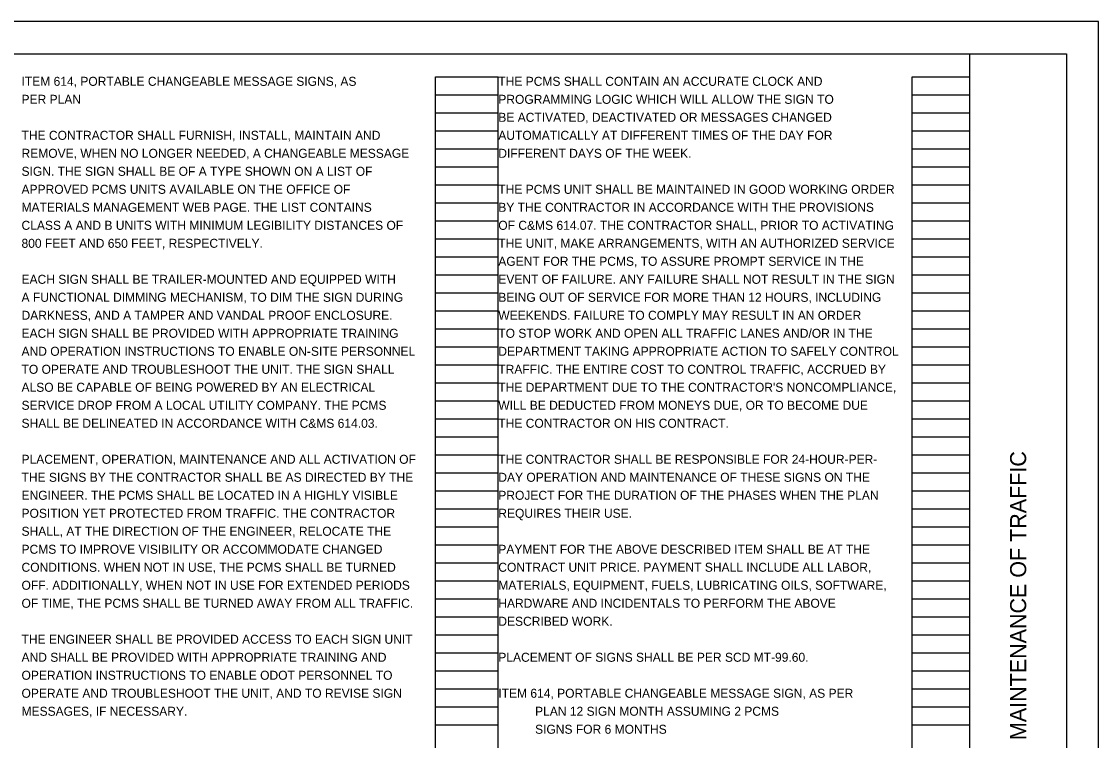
# Model space of a CAD drawing. Extents: x 0 to 34, y 0 to 22.
# Drawn here: x 17.24 to 34, y 10.82 to 22 of the extents above; entities that cross this region are included whole.
import ezdxf

# ---------------------------------------------------------------- set-up
doc = ezdxf.new("R2010")
doc.units = 0
for name, color, linetype in [('SH_Border', 7, 'Continuous'), ('SH_Cut_Line', 7, 'Continuous'), ('SH_Data', 7, 'Continuous'), ('SH_Text', 7, 'Continuous')]:
    doc.layers.add(name, color=color, linetype=linetype)

msp = doc.modelspace()

# ---------------------------------------------------------------- linework, layer by layer
at = {"layer": 'SH_Border'}
msp.add_line((32, 0.5), (32, 21.5), dxfattribs=at)
msp.add_lwpolyline([(1.5, 21.5), (33.5, 21.5), (33.5, 0.5), (1.5, 0.5)], close=True, dxfattribs=at)
at = {"layer": 'SH_Cut_Line'}
msp.add_lwpolyline([(0, 0), (34, 0), (34, 22), (0, 22)], close=True, dxfattribs=at)
at = {"layer": 'SH_Data'}
for p, q in [((23.68, 0.98), (23.68, 21.14)), ((23.68, 21.14), (24.66, 21.14)), ((24.66, 0.98), (24.66, 21.14)), ((31.1, 0.98), (31.1, 21.14)), ((31.1, 21.14), (32, 21.14)), ((32, 0.98), (32, 21.14)), ((23.68, 20.86), (24.66, 20.86)), ((31.1, 20.86), (32, 20.86)), ((23.68, 20.58), (24.66, 20.58)), ((31.1, 20.58), (32, 20.58)), ((23.68, 20.3), (24.66, 20.3)), ((31.1, 20.3), (32, 20.3)), ((23.68, 20.02), (24.66, 20.02)), ((31.1, 20.02), (32, 20.02)), ((23.68, 19.74), (24.66, 19.74)), ((31.1, 19.74), (32, 19.74)), ((23.68, 19.46), (24.66, 19.46)), ((31.1, 19.46), (32, 19.46)), ((23.68, 19.18), (24.66, 19.18)), ((31.1, 19.18), (32, 19.18)), ((23.68, 18.9), (24.66, 18.9)), ((31.1, 18.9), (32, 18.9)), ((23.68, 18.62), (24.66, 18.62)), ((31.1, 18.62), (32, 18.62)), ((23.68, 18.34), (24.66, 18.34)), ((31.1, 18.34), (32, 18.34)), ((23.68, 18.06), (24.66, 18.06)), ((31.1, 18.06), (32, 18.06)), ((23.68, 17.78), (24.66, 17.78)), ((31.1, 17.78), (32, 17.78)), ((23.68, 17.5), (24.66, 17.5)), ((31.1, 17.5), (32, 17.5)), ((23.68, 17.22), (24.66, 17.22)), ((31.1, 17.22), (32, 17.22)), ((23.68, 16.94), (24.66, 16.94)), ((31.1, 16.94), (32, 16.94)), ((23.68, 16.66), (24.66, 16.66)), ((31.1, 16.66), (32, 16.66)), ((23.68, 16.38), (24.66, 16.38)), ((31.1, 16.38), (32, 16.38)), ((23.68, 16.1), (24.66, 16.1)), ((31.1, 16.1), (32, 16.1)), ((23.68, 15.82), (24.66, 15.82)), ((31.1, 15.82), (32, 15.82)), ((23.68, 15.54), (24.66, 15.54)), ((31.1, 15.54), (32, 15.54)), ((23.68, 15.26), (24.66, 15.26)), ((31.1, 15.26), (32, 15.26)), ((23.68, 14.98), (24.66, 14.98)), ((31.1, 14.98), (32, 14.98)), ((23.68, 14.7), (24.66, 14.7)), ((31.1, 14.7), (32, 14.7)), ((23.68, 14.42), (24.66, 14.42)), ((31.1, 14.42), (32, 14.42)), ((23.68, 14.14), (24.66, 14.14)), ((31.1, 14.14), (32, 14.14)), ((23.68, 13.86), (24.66, 13.86)), ((31.1, 13.86), (32, 13.86)), ((23.68, 13.58), (24.66, 13.58)), ((31.1, 13.58), (32, 13.58)), ((23.68, 13.3), (24.66, 13.3)), ((31.1, 13.3), (32, 13.3)), ((23.68, 13.02), (24.66, 13.02)), ((31.1, 13.02), (32, 13.02)), ((23.68, 12.74), (24.66, 12.74)), ((31.1, 12.74), (32, 12.74)), ((23.68, 12.46), (24.66, 12.46)), ((31.1, 12.46), (32, 12.46)), ((23.68, 12.18), (24.66, 12.18)), ((31.1, 12.18), (32, 12.18)), ((23.68, 11.9), (24.66, 11.9)), ((31.1, 11.9), (32, 11.9)), ((23.68, 11.62), (24.66, 11.62)), ((31.1, 11.62), (32, 11.62)), ((23.68, 11.34), (24.66, 11.34)), ((31.1, 11.34), (32, 11.34)), ((23.68, 11.06), (24.66, 11.06)), ((31.1, 11.06), (32, 11.06))]:
    msp.add_line(p, q, dxfattribs=at)

# ---------------------------------------------------------------- texts
msp.add_text('MAINTENANCE OF TRAFFIC', height=0.25, rotation=90, dxfattribs=at).set_placement((32.875, 10.822))
at = {"layer": 'SH_Text'}
for s, p in [('ITEM 614, PORTABLE CHANGEABLE MESSAGE SIGNS, AS', (17.24, 21)), ('THE PCMS SHALL CONTAIN AN ACCURATE CLOCK AND', (24.66, 21)), ('PER PLAN', (17.24, 20.72)), ('PROGRAMMING LOGIC WHICH WILL ALLOW THE SIGN TO', (24.66, 20.72)), ('BE ACTIVATED, DEACTIVATED OR MESSAGES CHANGED', (24.66, 20.44)), ('THE CONTRACTOR SHALL FURNISH, INSTALL, MAINTAIN AND', (17.24, 20.16)), ('AUTOMATICALLY AT DIFFERENT TIMES OF THE DAY FOR', (24.66, 20.16)), ('REMOVE, WHEN NO LONGER NEEDED, A CHANGEABLE MESSAGE', (17.24, 19.88)), ('DIFFERENT DAYS OF THE WEEK.', (24.66, 19.88)), ('SIGN. THE SIGN SHALL BE OF A TYPE SHOWN ON A LIST OF', (17.24, 19.6)), ('APPROVED PCMS UNITS AVAILABLE ON THE OFFICE OF', (17.24, 19.32)), ('THE PCMS UNIT SHALL BE MAINTAINED IN GOOD WORKING ORDER', (24.66, 19.32)), ('MATERIALS MANAGEMENT WEB PAGE. THE LIST CONTAINS', (17.24, 19.04)), ('BY THE CONTRACTOR IN ACCORDANCE WITH THE PROVISIONS', (24.66, 19.04)), ('CLASS A AND B UNITS WITH MINIMUM LEGIBILITY DISTANCES OF', (17.24, 18.76)), ('OF C&MS 614.07. THE CONTRACTOR SHALL, PRIOR TO ACTIVATING', (24.66, 18.76)), ('800 FEET AND 650 FEET, RESPECTIVELY.', (17.24, 18.48)), ('THE UNIT, MAKE ARRANGEMENTS, WITH AN AUTHORIZED SERVICE', (24.66, 18.48)), ('AGENT FOR THE PCMS, TO ASSURE PROMPT SERVICE IN THE', (24.66, 18.2)), ('EACH SIGN SHALL BE TRAILER-MOUNTED AND EQUIPPED WITH', (17.24, 17.92)), ('EVENT OF FAILURE. ANY FAILURE SHALL NOT RESULT IN THE SIGN', (24.66, 17.92)), ('A FUNCTIONAL DIMMING MECHANISM, TO DIM THE SIGN DURING', (17.24, 17.64)), ('BEING OUT OF SERVICE FOR MORE THAN 12 HOURS, INCLUDING', (24.66, 17.64)), ('DARKNESS, AND A TAMPER AND VANDAL PROOF ENCLOSURE.', (17.24, 17.36)), ('WEEKENDS. FAILURE TO COMPLY MAY RESULT IN AN ORDER', (24.66, 17.36)), ('EACH SIGN SHALL BE PROVIDED WITH APPROPRIATE TRAINING', (17.24, 17.08)), ('TO STOP WORK AND OPEN ALL TRAFFIC LANES AND/OR IN THE', (24.66, 17.08)), ('AND OPERATION INSTRUCTIONS TO ENABLE ON-SITE PERSONNEL', (17.24, 16.8)), ('DEPARTMENT TAKING APPROPRIATE ACTION TO SAFELY CONTROL', (24.66, 16.8)), ('TO OPERATE AND TROUBLESHOOT THE UNIT. THE SIGN SHALL', (17.24, 16.52)), ('TRAFFIC. THE ENTIRE COST TO CONTROL TRAFFIC, ACCRUED BY', (24.66, 16.52)), ('ALSO BE CAPABLE OF BEING POWERED BY AN ELECTRICAL', (17.24, 16.24)), ("THE DEPARTMENT DUE TO THE CONTRACTOR'S NONCOMPLIANCE,", (24.66, 16.24)), ('SERVICE DROP FROM A LOCAL UTILITY COMPANY. THE PCMS', (17.24, 15.96)), ('WILL BE DEDUCTED FROM MONEYS DUE, OR TO BECOME DUE', (24.66, 15.96)), ('SHALL BE DELINEATED IN ACCORDANCE WITH C&MS 614.03.', (17.24, 15.68)), ('THE CONTRACTOR ON HIS CONTRACT.', (24.66, 15.68)), ('PLACEMENT, OPERATION, MAINTENANCE AND ALL ACTIVATION OF', (17.24, 15.12)), ('THE CONTRACTOR SHALL BE RESPONSIBLE FOR 24-HOUR-PER-', (24.66, 15.12)), ('THE SIGNS BY THE CONTRACTOR SHALL BE AS DIRECTED BY THE', (17.24, 14.84)), ('DAY OPERATION AND MAINTENANCE OF THESE SIGNS ON THE', (24.66, 14.84)), ('ENGINEER. THE PCMS SHALL BE LOCATED IN A HIGHLY VISIBLE', (17.24, 14.56)), ('PROJECT FOR THE DURATION OF THE PHASES WHEN THE PLAN', (24.66, 14.56)), ('POSITION YET PROTECTED FROM TRAFFIC. THE CONTRACTOR', (17.24, 14.28)), ('REQUIRES THEIR USE.', (24.66, 14.28)), ('SHALL, AT THE DIRECTION OF THE ENGINEER, RELOCATE THE', (17.24, 14)), ('PCMS TO IMPROVE VISIBILITY OR ACCOMMODATE CHANGED', (17.24, 13.72)), ('PAYMENT FOR THE ABOVE DESCRIBED ITEM SHALL BE AT THE', (24.66, 13.72)), ('CONDITIONS. WHEN NOT IN USE, THE PCMS SHALL BE TURNED', (17.24, 13.44)), ('CONTRACT UNIT PRICE. PAYMENT SHALL INCLUDE ALL LABOR,', (24.66, 13.44)), ('OFF. ADDITIONALLY, WHEN NOT IN USE FOR EXTENDED PERIODS', (17.24, 13.16)), ('MATERIALS, EQUIPMENT, FUELS, LUBRICATING OILS, SOFTWARE,', (24.66, 13.16)), ('OF TIME, THE PCMS SHALL BE TURNED AWAY FROM ALL TRAFFIC.', (17.24, 12.88)), ('HARDWARE AND INCIDENTALS TO PERFORM THE ABOVE', (24.66, 12.88)), ('DESCRIBED WORK.', (24.66, 12.6)), ('THE ENGINEER SHALL BE PROVIDED ACCESS TO EACH SIGN UNIT', (17.24, 12.32)), ('AND SHALL BE PROVIDED WITH APPROPRIATE TRAINING AND', (17.24, 12.04)), ('PLACEMENT OF SIGNS SHALL BE PER SCD MT-99.60.', (24.66, 12.04)), ('OPERATION INSTRUCTIONS TO ENABLE ODOT PERSONNEL TO', (17.24, 11.76)), ('OPERATE AND TROUBLESHOOT THE UNIT, AND TO REVISE SIGN', (17.24, 11.48)), ('ITEM 614, PORTABLE CHANGEABLE MESSAGE SIGN, AS PER', (24.66, 11.48)), ('MESSAGES, IF NECESSARY.', (17.24, 11.2)), ('           PLAN 12 SIGN MONTH ASSUMING 2 PCMS', (24.66, 11.2)), ('           SIGNS FOR 6 MONTHS', (24.66, 10.92))]:
    msp.add_text(s, height=0.14, dxfattribs=at).set_placement(p)

doc.saveas('drawing.dxf')
